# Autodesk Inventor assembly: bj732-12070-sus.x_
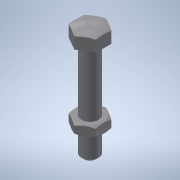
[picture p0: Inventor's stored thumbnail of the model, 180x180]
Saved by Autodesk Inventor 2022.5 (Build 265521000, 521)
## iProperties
Part Number: bj732-12070-sus.x_
Material: 一般
Document SubType Name: Assembly
Designer: ImaoCorp
Sending System: SOLIDWORKS 2017-2017317
MC: AMD64
MC_MODEL: Intel64 Family 6 Model 60 Stepping 3, GenuineIntel
OS: Windows_NT
FRU: Parasolid Version 29.0, build 201,  4-17-2017
FORMAT: text
GUISE: transmit
KEY: bj732-12070-sus
FILE: bj732-12070-sus.x_t
DATE: Fri Mar 15 10:10:25 2019
Author: ImaoCorp
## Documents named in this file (3)
- X:\14_SW2022-Inv2022\00_全2023-1023新製品(TCC)まで\b\bj732-12070-sus\BJ732-12070-SUS.iam
- X:\14_SW2022-Inv2022\00_全2023-1023新製品(TCC)まで\b\bj732-12070-sus\bj732-12070-sus_01.ipt
- X:\14_SW2022-Inv2022\00_全2023-1023新製品(TCC)まで\b\bj732-12070-sus\bj732-12070-sus_02.ipt
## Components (2 placed, 2 different names)
1. bj732-12070-sus_01
2. bj732-12070-sus_02
